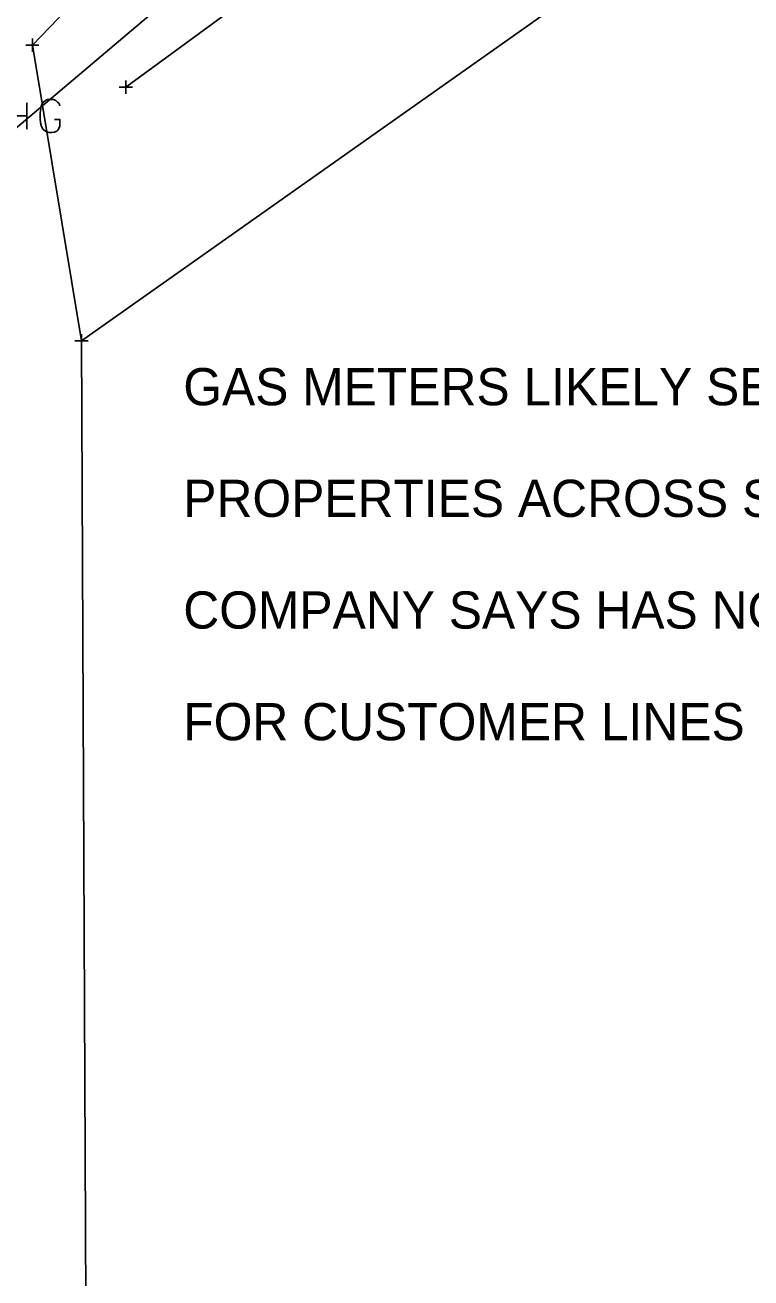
# Model space of a CAD drawing. Extents: x 2184635 to 2185378, y 369880 to 370486.
# Drawn here: x 2184969.9 to 2185024.5, y 370026.6 to 370120.8 of the extents above; entities that cross this region are included whole.
import ezdxf

# ---------------------------------------------------------------- set-up
doc = ezdxf.new("R2010")
doc.units = 0
for name, color, linetype in [('GE_X_Alignment_100_Bearings', 7, 'Continuous'), ('RD_X_Fence', 7, 'Continuous'), ('RW_X_CL', 7, 'Continuous'), ('SV_X_Break_Lines', 7, 'Continuous'), ('SV_X_Terrain_Boundary', 7, 'Continuous'), ('SV_X_Text', 7, 'Continuous'), ('UT_X_Gas', 7, 'Continuous')]:
    doc.layers.add(name, color=color, linetype=linetype)

msp = doc.modelspace()

# ---------------------------------------------------------------- linework, layer by layer
at = {"layer": 'GE_X_Alignment_100_Bearings'}
for p, q in [((2184970.044, 370112.98), (2184970.044, 370114.98)), ((2184970.044, 370113.98), (2184969.092, 370113.98))]:
    msp.add_line(p, q, dxfattribs=at)
msp.add_lwpolyline([(2184972.52, 370114.736), (2184972.5, 370114.834), (2184972.441, 370114.933), (2184972.343, 370115.031), (2184972.205, 370115.149), (2184972.107, 370115.189), (2184972.028, 370115.208), (2184971.91, 370115.228), (2184971.674, 370115.228), (2184971.575, 370115.208), (2184971.516, 370115.189), (2184971.437, 370115.149), (2184971.28, 370115.031), (2184971.182, 370114.893), (2184971.122, 370114.736), (2184971.083, 370114.52), (2184971.044, 370114.205), (2184971.044, 370113.791), (2184971.063, 370113.457), (2184971.142, 370113.201), (2184971.26, 370112.964), (2184971.359, 370112.886), (2184971.477, 370112.807), (2184971.693, 370112.728), (2184971.91, 370112.728), (2184972.126, 370112.768), (2184972.205, 370112.807), (2184972.284, 370112.846), (2184972.363, 370112.925), (2184972.441, 370113.043), (2184972.52, 370113.22), (2184972.52, 370113.712), (2184972.107, 370113.712)], dxfattribs=at)
at = {"layer": 'RD_X_Fence'}
msp.add_lwpolyline([(2184974.137, 370097.077), (2184970.447, 370119.306), (2184979.406, 370128.641), (2184992.607, 370140.381), (2185007.827, 370153.847), (2185011.099, 370157.209), (2185036.107, 370177.129), (2185063.41, 370198.922), (2185078.716, 370210.935), (2185113.226, 370240.316), (2185152.641, 370271.084), (2185187.441, 370299.506), (2185189.075, 370300.14), (2185213.006, 370319.114), (2185230.361, 370333.854), (2185268.576, 370364.897)], dxfattribs=at)
at = {"layer": 'RW_X_CL'}
for p, q in [((2184970.447, 370119.806), (2184970.447, 370118.806)), ((2184969.947, 370119.306), (2184970.947, 370119.306)), ((2184970.447, 370119.306), (2184970.447, 370119.306)), ((2184976.977, 370116.141), (2184977.977, 370116.141)), ((2184977.477, 370116.641), (2184977.477, 370115.641)), ((2184977.477, 370116.141), (2184977.477, 370116.141)), ((2184974.137, 370097.577), (2184974.137, 370096.577)), ((2184973.637, 370097.077), (2184974.637, 370097.077)), ((2184974.137, 370097.077), (2184974.137, 370097.077))]:
    msp.add_line(p, q, dxfattribs=at)
at = {"layer": 'SV_X_Break_Lines'}
msp.add_lwpolyline([(2184977.477, 370116.141), (2184988.511, 370124.248), (2184988.546, 370124.041), (2185011.422, 370131.8), (2185033.603, 370139.079)], dxfattribs=at)
at = {"layer": 'SV_X_Terrain_Boundary'}
msp.add_lwpolyline([(2184636.069, 369950.037), (2184651.151, 369938.985), (2184701.215, 369883.063), (2184720.068, 369902.68), (2184776.086, 369948.877), (2184881.346, 369949.865), (2184898.748, 369959.788), (2184956.333, 369996.082), (2184974.539, 370008.088), (2184974.137, 370097.077), (2185033.603, 370139.079)], dxfattribs=at)
at = {"layer": 'UT_X_Gas'}
msp.add_lwpolyline([(2184953.242, 370098.442), (2184967.159, 370111.339), (2184998.214, 370137.606), (2185039.424, 370172.123), (2185069.412, 370195.978), (2185086.695, 370210.093), (2185109.697, 370228.178), (2185131.189, 370247.901), (2185147.466, 370264.362), (2185212.955, 370317.623), (2185242.558, 370341.915), (2185269.196, 370362.683)], dxfattribs=at)

# ---------------------------------------------------------------- texts
at = {"layer": 'SV_X_Text'}
for s, p in [('GAS METERS LIKELY SERVICE', (2184981.801, 370092.216)), ('PROPERTIES ACROSS STATE ROUTE', (2184981.801, 370083.816)), ('COMPANY SAYS HAS NO RECORDS', (2184981.801, 370075.416)), ('FOR CUSTOMER LINES', (2184981.801, 370067.016))]:
    msp.add_text(s, height=2.8, dxfattribs=at).set_placement(p)

doc.saveas('drawing.dxf')
